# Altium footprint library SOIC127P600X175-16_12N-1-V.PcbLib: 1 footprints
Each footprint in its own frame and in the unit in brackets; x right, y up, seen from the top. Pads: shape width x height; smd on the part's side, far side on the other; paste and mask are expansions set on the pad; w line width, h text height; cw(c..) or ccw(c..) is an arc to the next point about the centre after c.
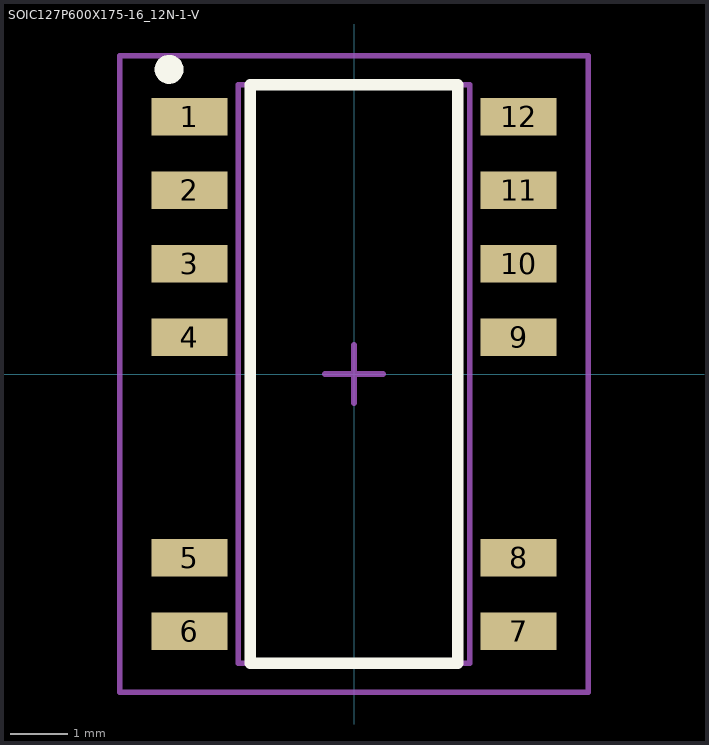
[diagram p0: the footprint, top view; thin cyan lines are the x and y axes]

## SOIC127P600X175-16_12N-1-V [mm] "SOIC,1.27mm pitch;12 pin,3.90mm W X 9.90mm L X 1.75mm H body"
height 1.75
pads (12):
  rect 1.31x0.65 smd paste+0 mask+0: 1(-2.845,4.445) 2(-2.845,3.175) 3(-2.845,1.905) 4(-2.845,0.635) 5(-2.845,-3.175) 6(-2.845,-4.445) 7(2.845,-4.445) 8(2.845,-3.175) 9(2.845,0.635) 10(2.845,1.905) 11(2.845,3.175) 12(2.845,4.445)
Top Overlay:
  circle w0.25: c-3.195,5.265 r0.125
  lines w0.2: -1.79,-5 -1.79,5 1.79,5 1.79,-5 -1.79,-5
M3 (ASY_Text_Top):
  text ".DESIGNATOR" at 0,0 h1.2
M13 (CMP_Body_OTL_Top):
  lines w0.1: -2,-5 -2,5 2,5 2,-5 -2,-5
M15 (CMP_Courtyard_Top):
  lines w0.1: -0.5,0 0.5,0 ; 0,-0.5 0,0.5 ; -4.05,-5.5 -4.05,5.5 4.05,5.5 4.05,-5.5 -4.05,-5.5
3D body "PG-DSO-12-20_C66065-A5468-C003-01-0004.stp": height 1.76, standoff 0, extent -3,-5 3,5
